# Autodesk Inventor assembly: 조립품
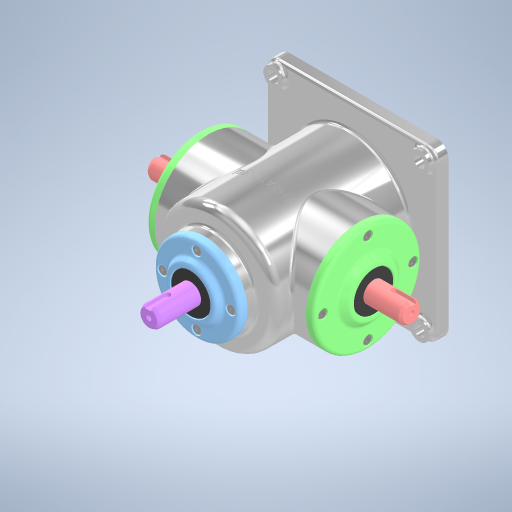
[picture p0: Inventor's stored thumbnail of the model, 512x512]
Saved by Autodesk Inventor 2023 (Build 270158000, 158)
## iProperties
Created: 2025-05
Part Number: 조립품
Document SubType Name: Assembly
Designer: Admin
Author: Admin
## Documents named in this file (13)
- C:\Users\Admin\Desktop\750505V1007\조립품.iam
- C:\Users\Admin\Desktop\750505V1007\본체.ipt
- C:\Users\Admin\Desktop\750505V1007\750505V1007\측면 커버.ipt
- C:\Users\Admin\Desktop\750505V1007\750505V1007\깊은 홈 볼 베어링 6203.ipt
- C:\Users\Admin\Desktop\750505V1007\750505V1007\오일 실 17 32 8.ipt
- C:\Users\Admin\Desktop\750505V1007\750505V1007\메인 축.ipt
- C:\Users\Admin\Desktop\750505V1007\750505V1007\평행 키 5x5.ipt
- C:\Users\Admin\Desktop\750505V1007\750505V1007\메인 베벨기어.ipt
- C:\Users\Admin\Desktop\750505V1007\750505V1007\6각 구멍붙이 볼트 M4-10L.ipt
- C:\Users\Admin\Desktop\750505V1007\750505V1007\윗 커버.ipt
- C:\Users\Admin\Desktop\750505V1007\750505V1007\평행 키 4x4.ipt
- C:\Users\Admin\Desktop\750505V1007\750505V1007\서브 베벨기어.ipt
- C:\Users\Admin\Desktop\750505V1007\750505V1007\서브 축.ipt
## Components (12 placed, 1 different names)
1. 6각 구멍붙이 볼트 M4-10L:1
2. 6각 구멍붙이 볼트 M4-10L:2
3. 6각 구멍붙이 볼트 M4-10L:3
4. 6각 구멍붙이 볼트 M4-10L:4
5. 6각 구멍붙이 볼트 M4-10L:5
6. 6각 구멍붙이 볼트 M4-10L:6
7. 6각 구멍붙이 볼트 M4-10L:7
8. 6각 구멍붙이 볼트 M4-10L:8
9. 6각 구멍붙이 볼트 M4-10L:9
10. 6각 구멍붙이 볼트 M4-10L:10
11. 6각 구멍붙이 볼트 M4-10L:11
12. 6각 구멍붙이 볼트 M4-10L:12
